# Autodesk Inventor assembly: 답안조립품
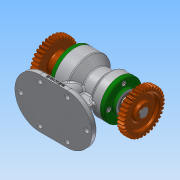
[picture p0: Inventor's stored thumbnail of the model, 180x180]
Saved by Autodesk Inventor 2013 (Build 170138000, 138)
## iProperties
Created: 2020-01
Part Number: 답안조립품
Document SubType Name: Assembly
Designer: Administrator
Author: Administrator
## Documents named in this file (13)
- C:\Users\Administrator\Desktop\700104V1015\답안조립품.iam
- C:\Users\Administrator\Desktop\700104V1015\본체.ipt
- C:\Users\Administrator\Desktop\700104V1015\Ű 5 x 5 x 18.ipt
- C:\Users\Administrator\Desktop\700104V1015\뒤커버.ipt
- C:\Users\Administrator\Desktop\700104V1015\멈춤나사 M3.ipt
- C:\Users\Administrator\Desktop\700104V1015\베어링 6203.ipt
- C:\Users\Administrator\Desktop\700104V1015\베어링 6205.ipt
- C:\Users\Administrator\Desktop\700104V1015\볼트 M4.ipt
- C:\Users\Administrator\Desktop\700104V1015\스퍼기어.ipt
- C:\Users\Administrator\Desktop\700104V1015\앞커버.ipt
- C:\Users\Administrator\Desktop\700104V1015\오일 실 17 30 8.ipt
- C:\Users\Administrator\Desktop\700104V1015\오일 실 25 38 8.ipt
- C:\Users\Administrator\Desktop\700104V1015\축.ipt
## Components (2 placed, 1 different names)
1. Ű 5 x 5 x 18:1
2. Ű 5 x 5 x 18:2
